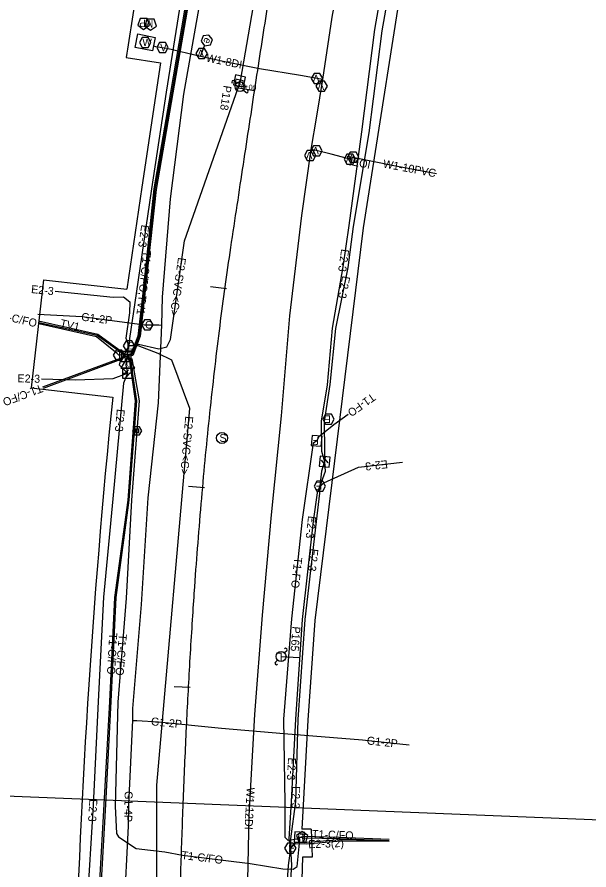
# Model space of a CAD drawing. Extents: x 1991878 to 2008544, y 770238 to 1141211.
# Drawn here: x 2007434.1 to 2007719.8, y 1137685.1 to 1138111.1 of the extents above; entities that cross this region are included whole.
import ezdxf

# ---------------------------------------------------------------- set-up
doc = ezdxf.new("R2010")
doc.units = 0
for name, color, linetype in [('RD_EX_SU_Elec', 7, 'Continuous'), ('RD_EX_SU_Gas', 7, 'Continuous'), ('RD_EX_SU_H2O', 7, 'Continuous'), ('RD_EX_SU_Misc', 7, 'Continuous'), ('RD_EX_SU_Pole', 7, 'Continuous'), ('RD_EX_SU_Sewer', 7, 'Continuous'), ('RD_EX_SU_SwpLmt', 7, 'Continuous'), ('RD_EX_SU_Telecom', 7, 'Continuous'), ('RD_EX_SU_TX_Elec', 7, 'Continuous'), ('RD_EX_SU_TX_Gas', 7, 'Continuous'), ('RD_EX_SU_TX_H2O', 7, 'Continuous'), ('RD_EX_SU_TX_Pole', 7, 'Continuous'), ('RD_EX_SU_TX_Telecom', 7, 'Continuous'), ('RD_HC_Cl', 7, 'Continuous')]:
    doc.layers.add(name, color=color, linetype=linetype)

msp = doc.modelspace()

# ---------------------------------------------------------------- linework, layer by layer
at = {"layer": 'RD_EX_SU_Elec'}
msp.add_line((2007565.97, 1137791.71), (2007575.04, 1137791.19), dxfattribs=at)
for points in [[(2007706.83, 1138822.62), (2007704.76, 1138818.43), (2007686.36, 1138768.29), (2007670.15, 1138718.93), (2007655.58, 1138671.59), (2007638.85, 1138621.77), (2007624.34, 1138576.36), (2007610.08, 1138534.72), (2007591.61, 1138479.18), (2007578.34, 1138428.3), (2007571.2, 1138401.76), (2007566.3, 1138382.49), (2007552.98, 1138327.8), (2007543.47, 1138281.15), (2007534.02, 1138228.49), (2007524.41, 1138175.98), (2007516.35, 1138122.86), (2007508.64, 1138073.54), (2007501.32, 1138025.38), (2007493.66, 1137973), (2007490.32, 1137950.52), (2007490.01, 1137946.93)], [(2007712.49, 1138542.43), (2007696.83, 1138494.53), (2007685.02, 1138446.06), (2007671.46, 1138399.73), (2007666.58, 1138380.33), (2007659.17, 1138349.31), (2007649.94, 1138302.21), (2007639.62, 1138255.08), (2007635.71, 1138237.27), (2007629.85, 1138204.64), (2007621.3, 1138154.75), (2007612.68, 1138104.93), (2007606.14, 1138053.84), (2007599.77, 1138007.06), (2007596.84, 1137986.3), (2007591.59, 1137955.78), (2007589.06, 1137927.38), (2007586.07, 1137909.2), (2007586.26, 1137894.25), (2007587.74, 1137889.07)], [(2007714.26, 1138542.06), (2007698.61, 1138494.14), (2007686.02, 1138445.77), (2007672.82, 1138398.47), (2007667.98, 1138379.97), (2007661.22, 1138349.15), (2007651.59, 1138301.88), (2007640.57, 1138254.66), (2007636.43, 1138237.15), (2007632.95, 1138204.15), (2007625.16, 1138154.04), (2007616.3, 1138104.21), (2007609.78, 1138053.19), (2007601.94, 1138006.51), (2007599.37, 1137985.94), (2007593.19, 1137955.57), (2007590.35, 1137927.51), (2007587.53, 1137909.08), (2007587.7, 1137893.93), (2007587.74, 1137889.07)], [(2007538.15, 1137074.35), (2007519.64, 1137210), (2007505.46, 1137340.1), (2007504.07, 1137566.44), (2007504, 1137727.5), (2007520.49, 1137915.5), (2007511.47, 1137939.68), (2007504.53, 1137943.1), (2007494.61, 1137946.88), (2007490.01, 1137946.93), (2007494.71, 1137947.7), (2007504.89, 1137945.37), (2007508.98, 1137946.44), (2007510.73, 1137950.05), (2007517.78, 1137999.33), (2007545.65, 1138079.09), (2007589.39, 1138331.96), (2007642.59, 1138527.53)], [(2007453.15, 1137974.12), (2007482.06, 1137971.27), (2007487.25, 1137971.36), (2007490.49, 1137968.93), (2007490.29, 1137963.41), (2007488.51, 1137950.75), (2007490.01, 1137946.93)], [(2007490.01, 1137946.93), (2007485.8, 1137939.57), (2007485.12, 1137937.45), (2007489.28, 1137933.15)], [(2007490.01, 1137946.93), (2007489.34, 1137944.11), (2007488.44, 1137937.24), (2007489.28, 1137933.15)], [(2007446.27, 1137930.37), (2007463.33, 1137929.94), (2007482.11, 1137930.6), (2007489.28, 1137933.15)], [(2007489.28, 1137933.15), (2007487.23, 1137928.22), (2007481.9, 1137870.54), (2007477.33, 1137821.26), (2007474.56, 1137769.27), (2007472.14, 1137717.53), (2007468.95, 1137665.87), (2007466.97, 1137611.83), (2007467.38, 1137561.4), (2007468.93, 1137510.87), (2007469.59, 1137460.78), (2007469.84, 1137408.14), (2007470.86, 1137359.78), (2007471.37, 1137336.79)], [(2007486.78, 1137933.15), (2007488.11, 1137933.15), (2007489.8, 1137934.84)], [(2007491.78, 1137933.15), (2007490.44, 1137933.15), (2007488.76, 1137931.46)], [(2007587.49, 1137886.58), (2007587.62, 1137887.91), (2007586.11, 1137889.75)], [(2007587.98, 1137891.55), (2007587.85, 1137890.23), (2007589.37, 1137888.38)], [(2007587.74, 1137889.07), (2007586.22, 1137884.34), (2007585.36, 1137876.84), (2007583.94, 1137873.41), (2007581.99, 1137859.36), (2007576.46, 1137810.21), (2007573.14, 1137760.34), (2007570.95, 1137719.22), (2007569.89, 1137700.53), (2007570.62, 1137695.92)], [(2007587.74, 1137889.07), (2007588.08, 1137884.19), (2007585.36, 1137876.84), (2007585.1, 1137873.36), (2007583.55, 1137859.09), (2007577.93, 1137810.14), (2007574.31, 1137760.17), (2007573.24, 1137719.2), (2007570.63, 1137700.7), (2007570.62, 1137695.92)], [(2007585.36, 1137876.84), (2007587.36, 1137878.51), (2007604.59, 1137886.22), (2007626.69, 1137888.74)], [(2007619.91, 1137699.61), (2007595.56, 1137700.14), (2007578.9, 1137698.79), (2007572.9, 1137698.63), (2007570.62, 1137695.92)], [(2007619.9, 1137699.22), (2007595.8, 1137699.54), (2007578.71, 1137698.01), (2007573.11, 1137698.06), (2007570.62, 1137695.92)], [(2007570.62, 1137695.92), (2007569.46, 1137687.25), (2007567.73, 1137661.27), (2007566.21, 1137611.95), (2007565.73, 1137562.4), (2007564.86, 1137512.09), (2007564.89, 1137463.95), (2007566.48, 1137412.78), (2007568.33, 1137361.93), (2007571.37, 1137337.7), (2007572.7, 1137334.91)], [(2007570.62, 1137695.92), (2007571.14, 1137687.4), (2007569.4, 1137661.42), (2007569.9, 1137611.67), (2007568.5, 1137562.25), (2007567.7, 1137512.09), (2007568.11, 1137464.12), (2007569.62, 1137413.08), (2007570.65, 1137362.21), (2007573.38, 1137338.26), (2007572.7, 1137334.91)]]:
    msp.add_lwpolyline(points, dxfattribs=at)
for points in [[(2007547.15, 1138076.24), (2007548.19, 1138081.13), (2007543.3, 1138082.18), (2007542.26, 1138077.29)], [(2007492.9, 1137946.93), (2007491.45, 1137949.43), (2007488.57, 1137949.43), (2007487.12, 1137946.93), (2007488.57, 1137944.43), (2007491.45, 1137944.43)], [(2007491.78, 1137935.65), (2007486.78, 1137935.65), (2007486.78, 1137930.65), (2007491.78, 1137930.65)], [(2007586.8, 1137910.25), (2007588.24, 1137907.75), (2007591.13, 1137907.75), (2007592.57, 1137910.25), (2007591.13, 1137912.75), (2007588.24, 1137912.75)], [(2007585.49, 1137891.8), (2007585, 1137886.82), (2007589.98, 1137886.33), (2007590.47, 1137891.31)], [(2007582.48, 1137876.84), (2007583.92, 1137874.34), (2007586.81, 1137874.34), (2007588.25, 1137876.84), (2007586.81, 1137879.34), (2007583.92, 1137879.34)], [(2007573.51, 1137695.92), (2007572.06, 1137698.42), (2007569.18, 1137698.42), (2007567.73, 1137695.92), (2007569.18, 1137693.42), (2007572.06, 1137693.42)]]:
    msp.add_lwpolyline(points, close=True, dxfattribs=at)
at = {"layer": 'RD_EX_SU_Gas'}
for points in [[(2007634.42, 1138570.59), (2007615.51, 1138521.62), (2007606.1, 1138472.02), (2007592.8, 1138417.02), (2007580.86, 1138378.9), (2007568.59, 1138323.23), (2007555.66, 1138269.15), (2007546.41, 1138226.42), (2007535.61, 1138173.44), (2007525.93, 1138121.66), (2007517.31, 1138072.53), (2007510.66, 1138020.37), (2007506.64, 1137971.23), (2007506.3, 1137957.32), (2007504.57, 1137918.34), (2007499.45, 1137870.97), (2007496.13, 1137817.71), (2007491.79, 1137765.75), (2007491.75, 1137759.97), (2007489.77, 1137717.72), (2007489.6, 1137706.9), (2007487.5, 1137663.95)], [(2007444.54, 1137962.71), (2007466.68, 1137961.45), (2007497.77, 1137957.43), (2007504.9, 1137957.32), (2007506.29, 1137957.25)], [(2007491.74, 1137759.68), (2007493.95, 1137759.67), (2007504.72, 1137759.03), (2007536.25, 1137755.96), (2007567.3, 1137753.25), (2007606.71, 1137750.06), (2007630.03, 1137747.55)]]:
    msp.add_lwpolyline(points, dxfattribs=at)
msp.add_lwpolyline([(2007500.66, 1137954.91), (2007502.1, 1137957.41), (2007500.66, 1137959.91), (2007497.77, 1137959.91), (2007496.33, 1137957.41), (2007497.77, 1137954.91)], close=True, dxfattribs=at)
at = {"layer": 'RD_EX_SU_H2O'}
for points in [[(2007548.97, 1137663.53), (2007550.1, 1137712.27), (2007552.81, 1137762.67), (2007556.77, 1137812.3), (2007561.23, 1137862.39), (2007566.19, 1137911.98), (2007570.32, 1137961.89), (2007576.38, 1138011.99), (2007581, 1138044.96), (2007583.81, 1138061.61), (2007586.91, 1138079.97), (2007591.59, 1138111.01), (2007600.73, 1138160.37), (2007610.7, 1138210.15), (2007620.53, 1138259.51), (2007630.19, 1138307.66), (2007640.83, 1138356.11), (2007652.92, 1138406.01), (2007664.84, 1138453.65), (2007678.31, 1138502.25), (2007692.96, 1138551.24)], [(2007502.34, 1138096.78), (2007503.35, 1138096.38), (2007508.93, 1138095.52), (2007525.72, 1138091.58), (2007537.94, 1138088.88), (2007555.27, 1138085.34), (2007575.65, 1138082), (2007585.84, 1138080.23), (2007586.93, 1138080.06)], [(2007525.83, 1138091.56), (2007525.92, 1138091.92), (2007527.81, 1138096.75)], [(2007601.25, 1138040.07), (2007599.12, 1138040.44), (2007591.01, 1138042.64), (2007582.81, 1138044.64), (2007580.99, 1138044.95)], [(2007599.12, 1138040.44), (2007599.25, 1138040.91), (2007599.37, 1138041.64), (2007603.52, 1138040.75), (2007621.52, 1138037.14), (2007643.67, 1138032.93)], [(2007599.97, 1138041.35), (2007601.44, 1138041.06), (2007600.68, 1138037.14), (2007599.2, 1138037.42)]]:
    msp.add_lwpolyline(points, dxfattribs=at)
for points in [[(2007497.32, 1138104.89), (2007500.22, 1138107), (2007499.11, 1138110.41), (2007495.53, 1138110.41), (2007494.42, 1138107)], [(2007500.8, 1138104.52), (2007503.7, 1138106.63), (2007502.59, 1138110.04), (2007499, 1138110.04), (2007497.9, 1138106.63)], [(2007494.48, 1138102.78), (2007503.17, 1138100.96), (2007501.82, 1138094.17), (2007493.04, 1138095.92)], [(2007527.81, 1138096.75), (2007530.66, 1138097.19), (2007531.71, 1138099.88), (2007529.91, 1138102.13), (2007527.05, 1138101.69), (2007526, 1138099.01)], [(2007501, 1138098.46), (2007499.56, 1138100.96), (2007496.67, 1138100.96), (2007495.23, 1138098.46), (2007496.67, 1138095.96), (2007499.56, 1138095.96)], [(2007509.66, 1138095.91), (2007508.22, 1138098.41), (2007505.33, 1138098.41), (2007503.89, 1138095.91), (2007505.33, 1138093.41), (2007508.22, 1138093.41)], [(2007523.42, 1138092.96), (2007524.86, 1138090.46), (2007527.75, 1138090.46), (2007529.19, 1138092.96), (2007527.75, 1138095.45), (2007524.86, 1138095.45)], [(2007581.07, 1138080.39), (2007582.51, 1138077.89), (2007585.4, 1138077.89), (2007586.84, 1138080.39), (2007585.4, 1138082.89), (2007582.51, 1138082.89)], [(2007583.43, 1138076.57), (2007584.87, 1138074.07), (2007587.76, 1138074.07), (2007589.2, 1138076.57), (2007587.76, 1138079.07), (2007584.87, 1138079.07)], [(2007580.82, 1138044.34), (2007582.26, 1138041.84), (2007585.15, 1138041.84), (2007586.59, 1138044.34), (2007585.15, 1138046.84), (2007582.26, 1138046.84)], [(2007577.64, 1138041.88), (2007579.08, 1138039.38), (2007581.97, 1138039.38), (2007583.41, 1138041.88), (2007581.97, 1138044.38), (2007579.08, 1138044.38)], [(2007597.46, 1138040.18), (2007598.9, 1138037.68), (2007601.79, 1138037.68), (2007603.23, 1138040.18), (2007601.79, 1138042.68), (2007598.9, 1138042.68)], [(2007599.09, 1138041.08), (2007600.53, 1138038.58), (2007603.42, 1138038.58), (2007604.86, 1138041.08), (2007603.42, 1138043.57), (2007600.53, 1138043.57)]]:
    msp.add_lwpolyline(points, close=True, dxfattribs=at)
at = {"layer": 'RD_EX_SU_Misc'}
msp.add_lwpolyline([(2007489.43, 1137941.78), (2007485.96, 1137935.78), (2007492.89, 1137935.78)], close=True, dxfattribs=at)
at = {"layer": 'RD_EX_SU_Pole'}
for p, q in [((2007542.66, 1138079.17), (2007543.72, 1138078.11)), ((2007547.26, 1138074.57), (2007548.32, 1138073.51)), ((2007568.8, 1137794.54), (2007567.74, 1137793.48)), ((2007564.2, 1137789.94), (2007563.14, 1137788.88))]:
    msp.add_line(p, q, dxfattribs=at)
for centre in [(2007545.49, 1138076.34), (2007565.97, 1137791.71)]:
    msp.add_circle(centre, 2.5, dxfattribs=at)
for centre, start, end in [((2007542.13, 1138078.64), 45, 225), ((2007548.85, 1138074.04), 225, 45), ((2007568.27, 1137795.07), 315, 135), ((2007563.67, 1137788.35), 135, 315)]:
    msp.add_arc(centre, 0.75, start, end, dxfattribs=at)
at = {"layer": 'RD_EX_SU_Sewer'}
for points in [[(2007496.42, 1137904.39), (2007495.26, 1137906.39), (2007492.95, 1137906.39), (2007491.8, 1137904.39), (2007492.95, 1137902.39), (2007495.26, 1137902.39)], [(2007494.92, 1137905.2), (2007493.29, 1137905.21), (2007493.29, 1137903.57), (2007494.92, 1137903.57)]]:
    msp.add_lwpolyline(points, close=True, dxfattribs=at)
msp.add_circle((2007536.45, 1137900.86), 2.75, dxfattribs=at)
at = {"layer": 'RD_EX_SU_SwpLmt'}
for p, q in [((2007488.69, 1138090.88), (2007505.82, 1138088.3)), ((2007447.25, 1137979.9), (2007441.15, 1137925.82)), ((2007447.25, 1137979.9), (2007488.93, 1137975.21)), ((2007441.15, 1137925.82), (2007481.87, 1137921.31)), ((2007581.06, 1137705.46), (2007576.38, 1137705.46)), ((2007581.06, 1137705.46), (2007581.48, 1137691.52)), ((2007581.48, 1137691.52), (2007576.72, 1137691.52)), ((2007576.72, 1137691.52), (2007576.72, 1137691.52))]:
    msp.add_line(p, q, dxfattribs=at)
for points in [[(2007715.28, 1138528.93), (2007690.88, 1138444.46), (2007666.14, 1138348.11), (2007656.52, 1138300.81), (2007630.12, 1138153.21), (2007606.92, 1138005.78), (2007592.75, 1137889.42)], [(2007505.82, 1138088.3), (2007496.37, 1138026.11), (2007488.93, 1137975.21)], [(2007592.75, 1137889.42), (2007582.93, 1137809.67), (2007579.33, 1137759.93), (2007576.38, 1137705.46)], [(2007576.72, 1137691.52), (2007571.29, 1137512.07), (2007571.69, 1137464.19), (2007573.2, 1137413.17), (2007578.1, 1137313.79)]]:
    msp.add_lwpolyline(points, dxfattribs=at)
for centre, radius, start, end in [((2011139.83, 1137542.45), 3692.1, 170.92287, 171.45757), ((2011516.22, 1137514.01), 4054.85, 174.23509, 182.91727)]:
    msp.add_arc(centre, radius, start, end, dxfattribs=at)
at = {"layer": 'RD_EX_SU_Telecom'}
for points in [[(2007627.59, 1138575.05), (2007614.5, 1138532.66), (2007595.23, 1138477.59), (2007579.66, 1138428.05), (2007574.13, 1138401.36), (2007569.16, 1138381.1), (2007559.54, 1138350.07), (2007553.63, 1138327.41), (2007548.17, 1138278.88), (2007536.03, 1138228.39), (2007525.7, 1138175.56), (2007519.11, 1138122.6), (2007510.79, 1138073.46), (2007502.45, 1138025.25), (2007496.97, 1137973.16), (2007494.45, 1137951.63), (2007491.1, 1137942.88), (2007488.59, 1137941.59)], [(2007628.19, 1138574.88), (2007615.18, 1138532.43), (2007595.94, 1138477.43), (2007580.19, 1138427.98), (2007574.61, 1138401.28), (2007569.71, 1138380.96), (2007560.17, 1138350.06), (2007554.14, 1138327.34), (2007548.86, 1138278.86), (2007536.67, 1138228.27), (2007526.24, 1138175.25), (2007519.69, 1138122.42), (2007511.37, 1138073.33), (2007502.97, 1138025.15), (2007497.48, 1137973.05), (2007494.94, 1137951.7), (2007491.53, 1137942.52), (2007485.03, 1137942.28)], [(2007628.91, 1138574.72), (2007615.65, 1138532.16), (2007596.75, 1138477.17), (2007580.91, 1138427.76), (2007575.16, 1138401.11), (2007570.39, 1138380.76), (2007560.7, 1138350.03), (2007554.69, 1138327.28), (2007549.53, 1138278.6), (2007537.28, 1138228.23), (2007526.8, 1138175.21), (2007520.39, 1138122.41), (2007511.93, 1138073.21), (2007503.52, 1138024.98), (2007498.02, 1137972.97), (2007495.54, 1137951.65), (2007491.98, 1137941.97), (2007488.59, 1137941.59)], [(2007488.59, 1137941.59), (2007486.84, 1137943.63), (2007474.42, 1137952.58), (2007444.9, 1137959.14)], [(2007488.59, 1137941.59), (2007486.42, 1137943.18), (2007474.08, 1137952.04), (2007444.93, 1137958.4)], [(2007485.03, 1137942.28), (2007484.19, 1137943.1), (2007473.82, 1137951.36), (2007444.97, 1137957.92)], [(2007488.59, 1137941.59), (2007485.54, 1137940.51), (2007446.77, 1137926.19)], [(2007488.59, 1137941.59), (2007486.02, 1137940.1), (2007447.1, 1137925.52)], [(2007488.59, 1137941.59), (2007490.31, 1137939.18), (2007493.11, 1137919.43), (2007489.45, 1137869.72), (2007482.81, 1137821.13), (2007480.28, 1137769.18), (2007477.48, 1137717.76), (2007474.5, 1137664.76), (2007471.59, 1137612.08), (2007472.97, 1137562.47), (2007473.73, 1137512.24), (2007474.56, 1137461.17), (2007474.48, 1137409.11), (2007475.63, 1137361.12), (2007476.12, 1137323.4), (2007474.75, 1137321.78), (2007473.11, 1137319.65)], [(2007488.59, 1137941.59), (2007490.83, 1137939.39), (2007493.71, 1137919.34), (2007490.01, 1137869.81), (2007483.39, 1137821.11), (2007480.99, 1137769.18), (2007478.3, 1137717.82), (2007475.28, 1137664.63), (2007472.43, 1137612.06), (2007473.73, 1137562.54), (2007474.57, 1137511.86), (2007475.27, 1137461.21), (2007475.32, 1137409.05), (2007476.43, 1137361.02), (2007476.96, 1137323.23), (2007475.05, 1137321.33), (2007473.11, 1137319.65)], [(2007488.59, 1137941.59), (2007491.4, 1137940.42), (2007495.06, 1137919.34), (2007491.23, 1137869.76), (2007488.55, 1137820.9), (2007484.41, 1137768.94), (2007483.14, 1137716.93), (2007483.78, 1137703.34), (2007484.83, 1137701.57), (2007493.54, 1137695.86), (2007507.85, 1137694.19), (2007516.69, 1137692.55), (2007550.48, 1137688.32), (2007566.81, 1137685.59), (2007572.06, 1137685.44), (2007574.01, 1137686.76), (2007575.36, 1137700.12), (2007575.17, 1137701.49)], [(2007599.49, 1137912.62), (2007592.3, 1137907.48), (2007584.74, 1137901.23), (2007583.77, 1137899.4)], [(2007575.17, 1137701.49), (2007574.01, 1137700.53), (2007569.51, 1137699.74), (2007568.09, 1137701.27), (2007567.99, 1137718.48), (2007567.33, 1137760.44), (2007571.31, 1137810.52), (2007576.64, 1137860.19), (2007582.26, 1137898.46), (2007582.93, 1137898.85), (2007583.77, 1137899.4)], [(2007575.17, 1137701.49), (2007577.55, 1137701.96), (2007594.84, 1137701.47), (2007619.92, 1137700.48)], [(2007576.54, 1137701.01), (2007577.74, 1137701.2), (2007595.05, 1137700.87), (2007619.91, 1137699.85)]]:
    msp.add_lwpolyline(points, dxfattribs=at)
for points in [[(2007487.91, 1137942.28), (2007486.47, 1137944.78), (2007483.58, 1137944.78), (2007482.14, 1137942.28), (2007483.58, 1137939.79), (2007486.47, 1137939.79)], [(2007491.09, 1137944.09), (2007486.09, 1137944.09), (2007486.09, 1137939.09), (2007491.09, 1137939.09)], [(2007581.08, 1137897.11), (2007586.07, 1137896.72), (2007586.46, 1137901.7), (2007581.47, 1137902.09)], [(2007577.86, 1137703.79), (2007572.87, 1137704.18), (2007572.49, 1137699.2), (2007577.47, 1137698.81)], [(2007576.55, 1137704.36), (2007573.7, 1137702.29), (2007574.79, 1137698.94), (2007578.32, 1137698.94), (2007579.41, 1137702.29)]]:
    msp.add_lwpolyline(points, close=True, dxfattribs=at)
at = {"layer": 'RD_HC_Cl'}
for p, q in [((2007544.8, 1138075.68), (2007552.71, 1138074.47)), ((2007530.73, 1137976.48), (2007538.66, 1137975.47)), ((2007519.76, 1137876.79), (2007527.73, 1137876.07)), ((2007512.52, 1137776.79), (2007520.51, 1137776.34)), ((2007215.49, 1137730.79), (2007819.97, 1137706.25))]:
    msp.add_line(p, q, dxfattribs=at)
msp.add_open_spline([(2008468.44, 1139784.65), (2008330.54, 1139636.27), (2008112.04, 1139402.61), (2008010.65, 1139269.99), (2007954.96, 1139181.47), (2007845.36, 1139006.33), (2007807.05, 1138915.36), (2007714.1, 1138721), (2007657.93, 1138535.69), (2007584.82, 1138278.81), (2007557.24, 1138105.93), (2007524.47, 1137887.62), (2007511.86, 1137606.6), (2007518.19, 1137380.97), (2007535.52, 1137158.14), (2007573, 1136960.76), (2007648.83, 1136694.4), (2007817.41, 1136298.79), (2008044.24, 1135795.68), (2008373.08, 1135014.28)], degree=2, dxfattribs=at)

# ---------------------------------------------------------------- texts
at = {"layer": 'RD_EX_SU_Elec'}
for height, rotation, p in [(4, 257.9388, (2007543.52, 1138080.81)), (3.75, 360, (2007488.87, 1137945.05)), (3.75, 180, (2007590.82, 1137912.13)), (3.75, 180, (2007586.5, 1137878.72)), (3.75, 360, (2007569.48, 1137694.04))]:
    msp.add_text('E', height=height, rotation=rotation, dxfattribs=at).set_placement(p)
at = {"layer": 'RD_EX_SU_Gas'}
msp.add_text('G', height=3.75, dxfattribs=at).set_placement((2007498.07, 1137955.53))
at = {"layer": 'RD_EX_SU_H2O'}
for s, height, rotation, p in [('P', 3.75, 180, (2007498.47, 1138109.82)), ('M', 3.75, 180, (2007502.17, 1138109.56)), ('W', 3.75, 0.0098, (2007496.73, 1138096.58)), ('e', 3.75, 248.6677, (2007528.03, 1138101.18)), ('V', 3.75, 180, (2007527.52, 1138094.83)), ('V', 3.75, 180, (2007585.17, 1138082.27)), ('V', 3.75, 180, (2007587.53, 1138078.45)), ('V', 3.75, 180, (2007581.74, 1138043.76)), ('V', 3.75, 180, (2007584.91, 1138046.21)), ('V', 3.75, 180, (2007603.18, 1138042.95)), ('V', 3.75, 180, (2007601.56, 1138042.05)), ('EOI', 4, 348.9475, (2007601.18, 1138037.04))]:
    msp.add_text(s, height=height, rotation=rotation, dxfattribs=at).set_placement(p)
msp.add_text('V', height=3.75, dxfattribs=at).set_placement((2007505.57, 1138094.04))
at = {"layer": 'RD_EX_SU_Misc'}
msp.add_text('U', height=2.4, dxfattribs=at).set_placement((2007488.67, 1137936.58))
at = {"layer": 'RD_EX_SU_Pole'}
for rotation, p in [(270, (2007543.56, 1138077.15)), (180, (2007566.78, 1137793.64))]:
    msp.add_text('L', height=4, rotation=rotation, dxfattribs=at).set_placement(p)
at = {"layer": 'RD_EX_SU_Sewer'}
msp.add_text('S', height=3.93, dxfattribs=at).set_placement((2007535.24, 1137898.9))
at = {"layer": 'RD_EX_SU_Telecom'}
for s, height, p in [('T', 3.75, (2007483.82, 1137940.41)), ('F', 4, (2007487.45, 1137939.59)), ('T', 3.75, (2007575.33, 1137699.14))]:
    msp.add_text(s, height=height, dxfattribs=at).set_placement(p)
for rotation, p in [(175.5572, (2007585.06, 1137901.31)), (355.5572, (2007573.89, 1137699.59))]:
    msp.add_text('F', height=4, rotation=rotation, dxfattribs=at).set_placement(p)
at = {"layer": 'RD_EX_SU_TX_Elec'}
for s, rotation, p in [('E2-3', 261.679, (2007496.24, 1138007.55)), ('E2-3', 261.9653, (2007596.06, 1137995.41)), ('E2-SVC<C>', 261.8608, (2007514.59, 1137991.19)), ('E2-3', 258.5024, (2007596.66, 1137982.07)), ('E2-3', 354.3592, (2007440.99, 1137973.27)), ('E2-3', 358.566, (2007434.29, 1137928.68)), ('E2-3', 264.7179, (2007484, 1137915.44)), ('E2-SVC<C>', 264.9879, (2007518.17, 1137911.9)), ('E2-3', 186.4949, (2007619.05, 1137889.79)), ('E2-3', 263.5806, (2007579.53, 1137862.1)), ('E2-3', 263.4403, (2007580.68, 1137845.7)), ('E2-3', 266.9605, (2007569.51, 1137741.29)), ('E2-3', 268.5065, (2007571.54, 1137727.05)), ('E2-3', 266.4692, (2007470.28, 1137720.59)), ('E2-3(2)', 2.088, (2007579.61, 1137695.93))]:
    msp.add_text(s, height=4, rotation=rotation, dxfattribs=at).set_placement(p)
at = {"layer": 'RD_EX_SU_TX_Gas'}
for s, rotation, p in [('G1-2P', 352.6241, (2007466.02, 1137959.52)), ('G1-2P', 354.4381, (2007500.89, 1137757.39)), ('G1-2P', 353.8488, (2007608.65, 1137747.84)), ('G1-4P', 269.0621, (2007487.88, 1137724.5))]:
    msp.add_text(s, height=4, rotation=rotation, dxfattribs=at).set_placement(p)
at = {"layer": 'RD_EX_SU_TX_H2O'}
for s, rotation, p in [('W1-8DI', 348.4448, (2007528.32, 1138088.92)), ('W1-10PVC', 349.2315, (2007616.66, 1138036.03)), ('W1-12DI', 266.9166, (2007548.86, 1137726.37))]:
    msp.add_text(s, height=4, rotation=rotation, dxfattribs=at).set_placement(p)
at = {"layer": 'RD_EX_SU_TX_Pole'}
for s, rotation, p in [('P118', 261.6319, (2007537.33, 1138077.14)), ('P165', 265.5032, (2007571.72, 1137806.85))]:
    msp.add_text(s, height=4, rotation=rotation, dxfattribs=at).set_placement(p)
at = {"layer": 'RD_EX_SU_TX_Telecom'}
for s, rotation, p in [('T1-C/FO,TV1', 263.9675, (2007497.15, 1137994.53)), ('T1-C/FO', 347.1859, (2007423.27, 1137960.75)), ('TV1', 347.4819, (2007455.35, 1137956.35)), ('T1-C/FO', 200.5277, (2007446.03, 1137927.7)), ('T1-FO', 215.5376, (2007611.34, 1137923.43)), ('T1-FO', 263.873, (2007572.61, 1137841.37)), ('T1-C/FO', 266.7824, (2007480.2, 1137803.56)), ('T1-C/FO', 265.2782, (2007485, 1137803.08)), ('T1-C/FO', 357.738, (2007581.35, 1137701.1)), ('T1-C/FO', 352.8671, (2007516.05, 1137690.61))]:
    msp.add_text(s, height=4, rotation=rotation, dxfattribs=at).set_placement(p)
at = {"layer": 'RD_HC_Cl'}
msp.add_text('20+00', height=2.5, rotation=351.3538, dxfattribs=at).set_placement((2007543.84, 1138075.82))

doc.saveas('drawing.dxf')
